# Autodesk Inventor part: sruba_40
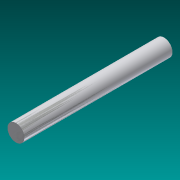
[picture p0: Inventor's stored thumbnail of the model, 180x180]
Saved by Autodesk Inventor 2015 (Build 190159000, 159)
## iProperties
Created: 2016-02
Part Number: sruba_40
Material: Generic
Document SubType Name: Modeling
Designer: Rafał
Density: 1 g/cm^3
Appearance: Aluminum - Flat
Author: Rafał
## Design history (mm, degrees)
sketch "Sketch1"
  geometry: C1 r 2 at (0, 0); 1 further point
  constraints: 1 centre point, 1 coincident
  dimensions: "d0" = 4 diameter of C1
extrude "Extrusion1" new body sketch "Sketch1" distance "d1" = 35; taper "d2" = 0 deg
body "Solid1"
